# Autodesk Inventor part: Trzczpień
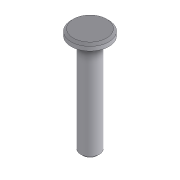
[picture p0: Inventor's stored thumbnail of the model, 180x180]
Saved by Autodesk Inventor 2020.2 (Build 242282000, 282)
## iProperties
Created: 2011-11
Part Number: Trzczpień
Material: Stal
Document SubType Name: Modeling
Designer: F.Stasiak
Density: 7.85 g/cm^3
Mass: 137.11 g
Surface Area: 55.0197 cm^2
Volume: 17.4662 cm^3
Appearance: Chrom — polerowany
Catalog Web Link: www.expertbooks.pl
Manager: www.cadconsulting.pl
Company: Fabian Stasiak CAD Consulting
Author: F.Stasiak
Subject: Zbiór ćwiczeń. Autodesk Inventor 2020. Kurs Professional
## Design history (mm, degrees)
sketch "Szkic1"
  geometry: C1 r 7.5 at (0, 0); 1 further point
  constraints: 1 centre point, 1 coincident
  dimensions: "d0" = 15 diameter of C1
extrude "Wyciągnięcie proste1" new body sketch "Szkic1" stored distance "d1" = 80; taper "d2" = 0 deg
sketch "Szkic2"
  geometry: C1 r 7.5 at (0, 0) reference; C2 r 15 at (0, 0)
  constraints: 1 centre point, 1 coincident
  dimensions: "d3" = 30 diameter of C2
extrude "Wyciągnięcie proste2" join sketch "Szkic2" distance "d4" = 5; taper "d5" = 0 deg
chamfer "Faza1" distance "d6" = 1.75; stored, may be unused: second distance "d7" = 2, angle "d8" = 45 deg
node "Bryła1"
